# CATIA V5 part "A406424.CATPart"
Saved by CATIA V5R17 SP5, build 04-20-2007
Part number: 06F5001R1910PN-158
Revision: -
Definition: A406424
Nomenclature: BACKSHELL, 90 DEG, SHRINK BOOT ACCOM, SELF-SEATING
Source: bought
Description: BACKSHELL, 90 DEG, SHRINK BOOT ACCOM, SELF-SEATING
Publications: "Logical Termination.1", "BCP", "BCP_generated(BCP)", "Face_generated(BCP)", "BaCP", "BaCP_generated(BaCP)", "Line.1_generated(BaCP)"
Material "Density=.2900": density 8027.17 kg/m3
Bounding box of the stored display mesh (mm): x -7.112 to 40.716, y -18.803 to 18.803, z -40.437 to 18.761
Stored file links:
  C:\Users\u305772\OneDrive - Gulfstream Aerospace\AD PAG\Harness\A406424.CATPart
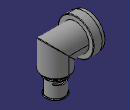
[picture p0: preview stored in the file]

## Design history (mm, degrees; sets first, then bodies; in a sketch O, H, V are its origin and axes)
Parameters
  PartNumber = "06F5001R1910PN-158"
  OtherKeywords = "BACKSHELL, 90 DEG, SHRINK BOOT ACCOM, SELF-SEATING"
  Comments = "1.102 x .039 in THREAD, ELECTROLESS NICKEL OVER STAINLESS STEEL."
  CAGECode = "07418"
  WeightComment = "SPEC"
  WeightSource = "SPEC"
  Volume = 1.31614e-05 (volume) {= smartVolume(Body1)}
  Density = 7916.45 (density)
  Weight = 0.229702 {= Volume *Density *2.20462262185}
  ExtraLength = 67.1576 mm {= E +F}
Set1
  Point1 "BCP": type Center, Curve edge [face of Shaft2 from Sketch7.L11 | face of Fillet1]
  Point2 "BaCP": type Center, Curve edge [face of Rib1 | face of Groove1 from Sketch4.L1]
  Point3: type Center, Curve edge [face of Groove1 from Sketch4.L2 | face of Slot1]
  Point4: (0, 0, 3.175), relative to Point2
  Line1: type PtPt, FirstPoint Point2, SecondPoint Point3
Body1 "PartBody" (main body)
  Sketch1 on zx-plane, origin (0, 0, 0), H (-1, 0, 0), V (0, 0, 1)
    point P1 (0, 0)
    line L1 (0, 0) -> (-26.7208, 0)
    line L2 (-26.7208, 0) -> (-26.7208, -18.0848)
    point P2 (-26.7208, -18.0848)
    point P4 (-26.7208, -40.4368)
    length L1 = 26.7208
    distance L1 P4 = 40.4368 {= F}
    distance P4 P2 = 22.352
    coincidence: P1 H, P1 V, P4 L2
    horizontal: L1 H
    perpendicularity: L1 L2
  Sketch2 on yz-plane, origin (0, 0, 0), H (0, 1, 0), V (0, 0, 1)
    circle A1 centre (0, 0) radius 13.9954
    construction line L1 (-13.9954, 0) -> (13.9954, 0)
    point P1 (-13.9954, 0)
    point P2 (13.9954, 0)
    length L1 = 27.9908
    coincidence: P1 A1, P1 H, A1 P2
    horizontal: L1 H
  Rib1: profile Sketch2, centre curve Sketch1
  Sketch3 on zx-plane, origin (0, 0, 0), H (-1, 0, 0), V (0, 0, 1)
    point P1 (-5.588, 14.0208)
    line L1 (-5.588, 14.0208) -> (-5.588, 18.8087)
    point P2 (-5.588, 18.8087)
    line L2 (-5.588, 18.8087) -> (3.4237, 18.8087)
    point P3 (3.4237, 18.8087)
    line L3 (3.4237, 18.8087) -> (3.937, 17.9197)
    point P4 (3.937, 17.9197)
    line L4 (3.937, 17.9197) -> (7.112, 17.9197)
    point P5 (7.112, 17.9197)
    line L5 (7.112, 17.9197) -> (7.112, 14.0208)
    point P6 (7.112, 14.0208)
    line L6 (7.112, 14.0208) -> (-5.588, 14.0208)
    axis line L7 (0, 0) -> (-5.588, 0)
    point P7 (-5.588, 0)
    point P8 (-5.588, -18.8087)
    point P9 (-5.588, -14.0208)
    construction line L8 (-5.588, -14.0208) -> (-5.588, -18.8087)
    point P10 (3.4237, -18.8087)
    construction line L9 (-5.588, -18.8087) -> (3.4237, -18.8087)
    point P11 (3.937, -17.9197)
    construction line L10 (3.4237, -18.8087) -> (3.937, -17.9197)
    point P12 (7.112, -17.9197)
    construction line L11 (3.937, -17.9197) -> (7.112, -17.9197)
    point P13 (7.112, -14.0208)
    construction line L12 (7.112, -17.9197) -> (7.112, -14.0208)
    construction line L13 (7.112, -14.0208) -> (-5.588, -14.0208)
    distance L5 L1 = 12.7
    length L4 = 3.175
    angle L4 L3 = 60
    distance L5 V = 7.112
    distance L6 L13 = 28.0416 {= `A THD` +.002 in}
    distance P5 P12 = 35.8394
    distance L4 L2 = 0.889
    vertical: L1 V, L5 V
    horizontal: L2 H, L4 H, L6 H, L7 H
    coincidence: P7 L1
    symmetry: P2 P8 L7, P1 P9 L7, L1 L8 L7, P3 P10 L7, L2 L9 L7, P4 P11 L7, L3 L10 L7, P5 P12 L7, L4 L11 L7, P6 P13 L7, L5 L12 L7, L6 L13 L7
  Shaft1: profile Sketch3, axis Sketch3.L7, angle 360
  Sketch4 on zx-plane, origin (0, 0, 0), H (-1, 0, 0), V (0, 0, 1)
    point P1 (0, 13.3604)
    line L1 (0, 13.3604) -> (-7.112, 13.3604)
    point P2 (-7.112, 13.3604)
    line L2 (-7.112, 13.3604) -> (-8.001, 12.4714)
    point P3 (-8.001, 12.4714)
    line L3 (-8.001, 12.4714) -> (-8.001, 0)
    point P4 (-8.001, 0)
    axis line L4 (-8.001, 0) -> (0, 0)
    line L5 (0, 0) -> (0, 13.3604)
    line L6 (0, 0) -> (-8.001, 0)
    point P5 (0, 0)
    point P6 (-8.001, 0)
    point P7 (-8.001, 0)
    point P8 (-8.001, -12.4714)
    construction line L7 (-8.001, -12.4714) -> (-8.001, 0)
    point P9 (-7.112, -13.3604)
    construction line L8 (-7.112, -13.3604) -> (-8.001, -12.4714)
    point P10 (0, -13.3604)
    construction line L9 (0, -13.3604) -> (-7.112, -13.3604)
    point P11 (0, 0)
    construction line L10 (0, 0) -> (0, -13.3604)
    construction line L11 (0, 0) -> (-8.001, 0)
    angle L1 L2 = 45
    length L1 = 7.112
    length L6 = 8.001
    distance L1 L9 = 26.7208 {= `A THD` -.05in}
    distance P8 P3 = 24.9428 (reference)
    coincidence: P1 V, P4 H, O L5, P4 L3, L6 L11
    horizontal: L1 H, L4 H, L6 H
    vertical: L3 V, L5 V
    symmetry: P6 P7 L4, P3 P8 L4, L3 L7 L4, P2 P9 L4, L2 L8 L4, P1 P10 L4, L1 L9 L4, P5 P11 L4, L5 L10 L4, L6 L11 L4
  Groove1: profile Sketch4, axis Sketch4.L4, angle 360
  Sketch5 on face of Groove1 from Sketch4.L3, origin (8.001, 0, 0), H (0, -1, 0), V (0, 0, 1)
    circle A1 centre (0, 0) radius 12.4714
    reference projected circle E1 centre (0, 0) radius 12.4714 from edge [face of Groove1 from Sketch4.L3 | face of Groove1 from Sketch4.L2]
    tangency: E1 A1
  Sketch6 on zx-plane, origin (0, 0, 0), H (-1, 0, 0), V (0, 0, 1)
    point P1 (-8.001, 0)
    line L1 (-8.001, 0) -> (-26.7208, 0)
    line L2 (-26.7208, 0) -> (-26.7208, -18.0848)
    point P3 (-26.7208, -18.0848)
    reference projected line E1 through (-26.7208, 13.0492) direction (0, -1) from axis of face of Rib1
    reference projected line E2 (-24.7252, -18.0848) -> (-36.7241, -18.0848) from edge [face of Rib1 | face of Rib1]
    reference intersected line E3 (-8.001, -4.4755) -> (-8.001, 4.4755) from face of Groove1 from Sketch4.L3
    coincidence: P1 H, L2 E1, P3 E2, P1 E3
    horizontal: L1 H
  Slot1: profile Sketch5, centre curve Sketch6
  Sketch7 on zx-plane, origin (0, 0, 0), H (-1, 0, 0), V (0, 0, 1)
    axis line L1 (-26.7208, 0) -> (-26.7208, -40.4368)
    point P1 (-26.7208, 0)
    point P2 (-26.7208, -40.4368)
    point P3 (-18.7833, -40.4368)
    line L2 (-18.7833, -40.4368) -> (-18.7833, -16.8148)
    point P4 (-18.7833, -16.8148)
    line L3 (-18.7833, -16.8148) -> (-14.2494, -16.8148)
    line L4 (-16.6053, -18.0848) -> (-16.6053, -21.5138)
    line L5 (-16.6053, -21.5138) -> (-15.6464, -21.5138)
    point P5 (-15.6464, -21.5138)
    line L6 (-15.6464, -21.5138) -> (-15.6464, -22.7838)
    point P6 (-15.6464, -22.7838)
    line L7 (-15.6464, -22.7838) -> (-17.5641, -22.7838)
    point P7 (-17.5641, -22.7838)
    line L8 (-17.5641, -22.7838) -> (-17.5641, -39.1668)
    point P8 (-17.5641, -39.1668)
    line L9 (-17.5641, -39.1668) -> (-16.6053, -39.1668)
    point P9 (-16.6053, -39.1668)
    line L10 (-16.6053, -39.1668) -> (-16.6053, -40.4368)
    point P10 (-16.6053, -40.4368)
    line L11 (-16.6053, -40.4368) -> (-18.7833, -40.4368)
    point P11 (-34.6583, -16.8148)
    point P13 (-37.7952, -21.5138)
    point P14 (-37.7952, -22.7838)
    point P15 (-35.8775, -22.7838)
    construction line L12 (-34.6583, -16.8148) -> (-36.8364, -16.8148)
    construction line L13 (-36.8364, -16.8148) -> (-36.8364, -21.5138)
    construction line L14 (-36.8364, -21.5138) -> (-37.7952, -21.5138)
    construction line L15 (-37.7952, -21.5138) -> (-37.7952, -22.7838)
    construction line L16 (-37.7952, -22.7838) -> (-35.8775, -22.7838)
    point P16 (-34.6583, -40.4368)
    construction line L17 (-34.6583, -40.4368) -> (-34.6583, -16.8148)
    point P17 (-35.8775, -39.1668)
    construction line L18 (-35.8775, -22.7838) -> (-35.8775, -39.1668)
    point P18 (-36.8364, -39.1668)
    construction line L19 (-35.8775, -39.1668) -> (-36.8364, -39.1668)
    point P19 (-36.8364, -40.4368)
    construction line L20 (-36.8364, -39.1668) -> (-36.8364, -40.4368)
    construction line L21 (-36.8364, -40.4368) -> (-34.6583, -40.4368)
    reference projected line E1 through (-26.7208, 13.0492) direction (0, -1) from axis of face of Rib1
    reference projected line E2 (-24.7252, -18.0848) -> (-36.7241, -18.0848) from edge [face of Rib1 | face of Rib1]
    reference projected line E3 (-24.7252, -18.0848) -> (-36.7241, -18.0848) from edge [face of Rib1 | face of Rib1]
    line L22 (-16.6053, -18.0848) -> (-14.2494, -18.0848)
    point P23 (-14.2494, -18.0848)
    line L23 (-14.2494, -18.0848) -> (-14.2494, -16.8148)
    point P24 (-14.2494, -16.8148)
    point P25 (-39.1922, -16.8148)
    point P26 (-39.1922, -18.0848)
    construction line L24 (-39.1922, -18.0848) -> (-39.1922, -16.8148)
    reference intersected line E4 (-24.7252, -18.0848) -> (-36.7241, -18.0848) from face of Rib1
    length L1 = 40.4368
    length L10 = 1.27
    length L6 = 1.27
    distance L2 L17 = 15.875
    distance L8 L18 = 18.3134
    distance L6 L15 = 22.1488
    distance E2 L5 = 3.429
    distance L3 E3 = 1.27
    distance L24 L23 = 24.9428 {= Sketch4.distance(P8 P3)}
    coincidence: H P1, L11 P2, E1 L1, L22 E4
    perpendicularity: L3 L2, L8 L7
    parallelism: L4 L2, L7 L5, L9 L7, L10 L6, L11 L7, L22 L12, L23 L6
    symmetry: P4 P11 L1, P5 P13 L1, P6 P14 L1, P7 P15 L1, L3 L12 L1, L4 L13 L1, L5 L14 L1, L6 L15 L1, L7 L16 L1, P3 P16 L1, L2 L17 L1, P8 P17 L1, L8 L18 L1, P9 P18 L1, L9 L19 L1, P10 P19 L1, L10 L20 L1, L11 L21 L1, L18 L15 L20, P24 P25 L1, P23 P26 L1, L23 L24 L1, L6 L8 L4
  Shaft2: profile Sketch7, axis Sketch7.L1, angle 360
  Sketch8 on zx-plane, origin (0, 0, 0), H (-1, 0, 0), V (0, 0, 1)
    arc A1 centre (-33.3883, -26.0858) radius 1.27 from (-33.3883, -24.8158) to (-33.3883, -27.3558) ccw
    arc A2 centre (-20.0533, -26.0858) radius 1.27 from (-20.0533, -27.3558) to (-20.0533, -24.8158) ccw
    construction line L1 (-20.0533, -26.0858) -> (-33.3883, -26.0858)
    reference projected line E1 (-29.7557, -22.7838) -> (-39.2045, -22.7838) from edge [face of Shaft2 from Sketch7.L6 | face of Shaft2 from Sketch7.L7]
    line L2 (-33.3883, -24.8158) -> (-20.0533, -24.8158)
    line L3 (-20.0533, -27.3558) -> (-33.3883, -27.3558)
    reference projected line E2 (-29.7557, -22.7838) -> (-39.2045, -22.7838) from edge [face of Shaft2 from Sketch7.L6 | face of Shaft2 from Sketch7.L7]
    construction line L4 (-26.7208, -27.3558) -> (-26.7208, -24.8158)
    point P7 (-26.7208, -27.3558)
    point P8 (-26.7208, -24.8158)
    reference projected line E3 through (-26.7208, 13.0492) direction (0, -1) from axis of face of Shaft2 from Sketch7.L8
    distance L2 E2 = 2.032
    distance L2 L3 = 2.54
    distance A2 A1 = 15.875 {= `X DIA`}
    parallelism: E1 L1, L2 L1, L3 L1
    tangency: L2 A2, L2 A1, A1 L3, L3 A2
    midpoint: P7 L3, P8 L2
    perpendicularity: L4 L2
    coincidence: L4 E3
  Pocket1: profile Sketch8, direction (0, -1, 0), through (limit type 6), opposite side through (limit type 6)
  Fillet1: radius 0.508, on edge [face of Rib1 | face of Rib1]; edge [face of Shaft1 from Sketch3.L2 | face of Shaft1 from Sketch3.L1]; edge [face of Shaft2 from Sketch7.L5 | face of Shaft2 from Sketch7.L6]; edge [face of Shaft2 from Sketch7.L6 | face of Shaft2 from Sketch7.L7]; edge [face of Shaft2 from Sketch7.L9 | face of Shaft2 from Sketch7.L10]; edge [face of Shaft2 from Sketch7.L10 | face of Shaft2 from Sketch7.L11]; edge [face of Shaft2 from Sketch7.L11 | face of Shaft2 from Sketch7.L2]; edge [face of Rib1 | face of Shaft2]; edge [face of Shaft2 from Sketch7.L2 | face of Shaft2 from Sketch7.L3]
